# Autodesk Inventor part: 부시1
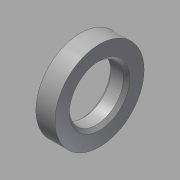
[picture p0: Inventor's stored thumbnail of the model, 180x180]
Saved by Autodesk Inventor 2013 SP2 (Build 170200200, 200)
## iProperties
Created: 2015-09
Part Number: 부시1
Material: 강철, 연강
Document SubType Name: Modeling
Designer: mduedu
Density: 7.86 g/cm^3
Description: 외주 가공
Mass: 17.8983 g
Surface Area: 15.6581 cm^2
Volume: 2.27713 cm^3
Author: mduedu
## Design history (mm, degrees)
sketch "스케치1"
  geometry: C1 r 14 at (0, 0); C2 r 8.5 at (0, 0); 1 further point
  constraints: 2 centre point, 2 coincident
  dimensions: "d0" = 28 diameter of C1; "d2" = 17 diameter of C2
extrude "돌출1" new body sketch "스케치1" distance "d3" = 6; taper "d4" = 0 deg
chamfer "모따기1" distance "d5" = 1; stored, may be unused: second distance "d6" = 2, angle "d7" = 45 deg
node "솔리드1"
